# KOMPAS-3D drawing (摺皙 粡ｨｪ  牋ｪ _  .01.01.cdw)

Views: Проекционный вид 2, Проекционный вид 4, Проекционный вид 5, Изометрия XYZ 7, Спереди 8, Спереди, Проекционный вид 9, Проекционный вид 10, Проекционный вид 11, Проекционный вид 12, Проекционный вид 13, Изометрия XYZ 14, Вид 15, Изометрия XYZ, Разрез А-А, Разрез Б-Б
Referenced files in C:\Users\s.slezkin\Desktop\Раскатчик арок 2\: Раскатчик арок _ А.01.01.a3d, Втулка ролика _ A.00.09.m3d, Вилка ролика _ A.00.08.m3d, Ролик _ А.00.00.01.m3d, Пластина крепления _ А.00.01.m3d, Пластина крепления штанги _ А.00.02.m3d, Опорная втулка вала _ A.00.04.m3d, Штанга №1 _ A.00.03.m3d, Направляющая вала _ A.00.05.m3d, Вал _ A.00.06.m3d, Штанга №2 _ A.00.07.m3d, Раскатчик арок _ А.01.01.cdw
Referenced files in C:\Program Files (x86)\ASCON\KOMPAS-3D V15\Libs\PartLib\DATA\vault\Methods\Kompas\3D\: PLib_Bolt_1_900.m3d, PLib_Washer_1_712.m3d, PLib_Nut_OST92_900.m3d, PLib_Nut_2_900.m3d, PLib_Splint_712.m3d, PLib_Blind_Nut_type1_900.m3d, PLib_Wing_Screw_DIN_1100.m3d
Referenced files: GRAPHIC.TDP
Referenced files in C:\Program Files (x86)\ASCON\KOMPAS-3D V15\Libs\PartLib\DATA\vault\Methods\Kompas\3D\Fastening_GOST\21331_37\: PLib_Screws_with_bead_GOST_21331_911.m3d
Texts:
  Раскатчик арок
  http://vk.com/sergey_krd
  Пластина крепления
  Пластина крепления штанги
  Опорная втулка вала
  Шайба 2.8.37 ГОСТ 11371-78
  Крепежное изделие ГОСТ
  Шайба
  ГОСТ
  АД1 ГОСТ 4784-97
  Болт М8x20 ГОСТ 15591-70
  Болт
  Штанга №1
  Направляющая вала
  Болт М8x70 ГОСТ 15591-70
  Гайка М8-6H ГОСТ 5915-70
  Гайка
  Вал
  Гайка М8-6H ГОСТ 5932-73
  Шплинт 1,6x16.4 ГОСТ 397-79
  Шплинт
  АМц ГОСТ 4784-97
  Болт М10x180 ГОСТ 15591-70
  Гайка М10-6H(S16)  ГОСТ 11860-85
  Штанга №2
  Wing screw DIN 316-М10 x 20-A
  Wing screw
  DIN
  Stainless steel
  Вилка ролика
  Винт B3.М10x60 ГОСТ 21331-75
  Винт
  Втулка ролика
  Колесо от рохли 70х80
  Шайба 2.10.37 ГОСТ 11371-78
  Лит-Масса-Масштаб
  Материал-Предприятие
  Title Specification
  Body Specification ( left align )
  Body Specificaton ( centered )
  Поз.
  Кол.
  Приме-
  чание
  Таблица спецификации
  Гайка М10-6H ГОСТ 2524-70
  Гайка М10-6H (S16) ГОСТ 11860-85
  Wing screw DIN 316 - M10 x 20 - A
Dimensions and other numbers on the sheet: 2; 6; 9; 13; 19; 14; 15; 20; 1; 3; 8; 10; 12; 16; 4; 5; 11; 18; 7; 17; 21; 0.332571; 37; 40Х; 019; 58; 1:1; 3,41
